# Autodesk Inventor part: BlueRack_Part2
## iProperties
Shininess: 64.0
Length Units: 11272
Angle Units: 11279
Time Units: 11290
Mass Units: 11286
Length Display Precision: 3
Angle Display Precision: 2
Compacted: True
Part Number: BlueRack_Part2
Document SubType Name: Modeling
Created: 2004-12
Designer: John Blackburn
Material: Steel, Mild
Manufacturer: Standard
Standards Organization: Custom
Density: 0.0
Volumn: 0.0
Area: 0.0
PropertySet Name: Model Information
Control State: 0
Master: False
Checked Out: False
Author: John Blackburn
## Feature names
1. Extrusion1
2. Hole1
3. Rectangular Pattern1
4. Hole3
5. Rectangular Pattern3
6. Hole4
7. Rectangular Pattern4
